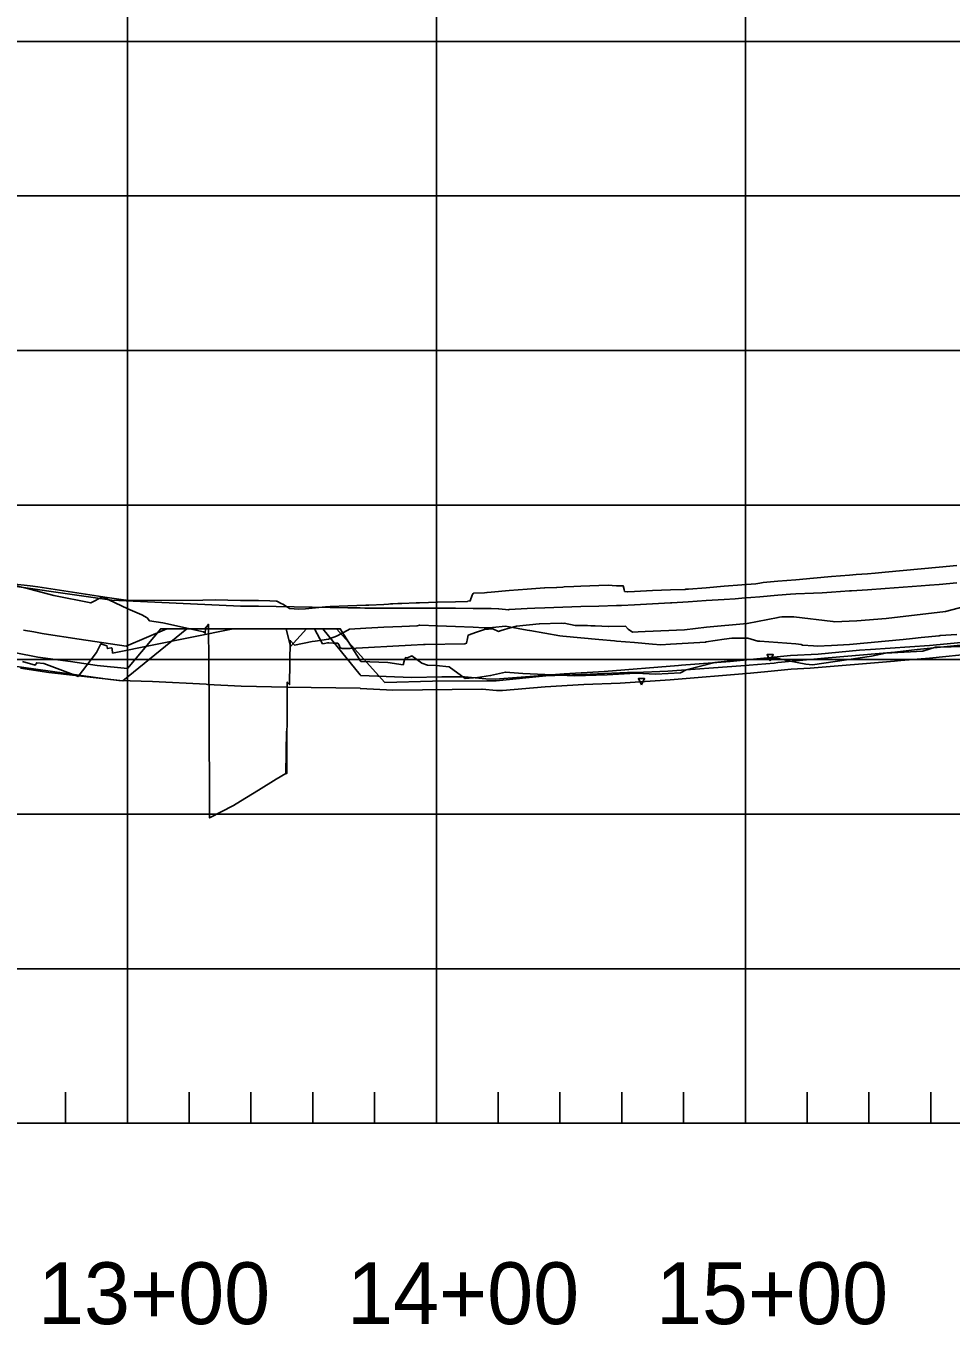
# Model space of a CAD drawing. Extents: x 704797 to 712284, y 374940 to 376945.
# Drawn here: x 708400.9 to 708700.2, y 375160.2 to 375580.5 of the extents above; entities that cross this region are included whole.
import ezdxf

# ---------------------------------------------------------------- set-up
doc = ezdxf.new("R2010")
doc.units = 0
for name, color, linetype in [('10', 7, 'Continuous'), ('12', 7, 'Continuous'), ('13', 7, 'Continuous'), ('61', 7, 'Continuous'), ('63', 7, 'Continuous'), ('Existing', 7, 'Continuous')]:
    doc.layers.add(name, color=color, linetype=linetype)

msp = doc.modelspace()

# ---------------------------------------------------------------- linework, layer by layer
at = {"layer": '10'}
for points in [[(708715.31, 375395.49), (708698.44, 375391.04), (708679.27, 375388.8), (708669.77, 375388.06), (708662.47, 375387.69), (708662.05, 375387.83), (708649.33, 375389.29), (708645.46, 375389.29), (708644.75, 375389.2), (708644.28, 375389.12), (708634.22, 375387.2), (708621.16, 375386), (708614.04, 375385.15), (708601.26, 375384.58), (708599.05, 375384.46), (708597.12, 375384.35), (708596.73, 375384.68), (708596.17, 375385.04), (708595.73, 375385.27), (708594.9, 375386.27), (708589.46, 375386.18), (708589.43, 375386.18), (708585.05, 375386.37), (708583.67, 375386.45), (708582.63, 375386.49), (708579.54, 375386.55), (708578.61, 375386.54), (708575.1, 375387.21), (708574.98, 375387.2), (708574.08, 375387.29), (708567.06, 375387.06), (708566.99, 375387.03), (708559.61, 375386.34), (708557.61, 375385.77), (708554.7, 375384.86), (708553.84, 375384.6), (708551.96, 375385.43), (708549.23, 375385.21), (708546.67, 375384.34), (708544, 375383.42), (708543.78, 375382.31), (708543.49, 375380.83), (708542.9, 375380.62), (708530.03, 375380.32), (708529.52, 375380.31), (708525.52, 375380.18), (708505.77, 375379.09), (708503.24, 375379.01), (708502.6, 375379.26), (708502.55, 375379.27), (708502.25, 375380.16), (708501.76, 375380.78), (708500.3, 375380.84), (708498.9, 375380.87), (708498.47, 375380.88), (708497.45, 375380.69), (708496.86, 375380.59), (708494.26, 375385.47), (708493.75, 375385.47), (708493.25, 375385.47), (708492.78, 375385.47), (708492.44, 375385.47), (708492.34, 375385.47), (708491.68, 375385.47), (708486.45, 375379.69), (708485.13, 375385.47), (708483.66, 375385.47), (708482.96, 375385.47), (708482.26, 375385.47), (708480.13, 375385.47), (708470.9, 375385.47), (708456.29, 375385.47), (708446.43, 375385.47), (708433.3, 375379.83), (708433.25, 375379.82), (708418.07, 375382.11), (708406.74, 375383.82), (708406.15, 375383.91), (708403.38, 375384.42), (708400.09, 375384.97)], [(708399.74, 375374.83), (708403.87, 375373.68), (708404.35, 375374.46), (708406.66, 375374.26), (708416.18, 375370.6), (708417.75, 375369.99), (708423.72, 375377.78), (708425.07, 375380.6), (708427.06, 375379.94), (708427.24, 375379.04), (708428.49, 375379.28), (708428.63, 375379.15), (708428.73, 375378.94), (708428.88, 375377.56), (708467.92, 375385.47), (708502.56, 375385.47), (708509.27, 375374.88), (708518.03, 375374.57), (708522.92, 375373.81), (708523.34, 375375.43), (708523.77, 375376.13), (708524.36, 375376.02), (708525.71, 375376.64), (708528.99, 375374.37), (708530.85, 375373.63), (708533.58, 375373.54), (708537.78, 375373.12), (708543.02, 375369.34), (708546.99, 375369.68), (708551.22, 375370.29), (708556.01, 375371.41), (708561.7, 375370.97), (708578.43, 375370.22), (708589, 375370.55), (708598.16, 375371.04), (708598.39, 375371.05), (708604.7, 375370.79), (708612.65, 375371.23), (708614.53, 375372.14), (708623.8, 375374.49), (708627.82, 375374.94), (708643.39, 375376.09), (708647.69, 375375.08), (708653.26, 375373.97), (708655.37, 375373.74), (708674.49, 375376.61), (708679.08, 375377.54), (708691.09, 375378.17), (708695.19, 375379.52), (708715.38, 375379.96)]]:
    msp.add_lwpolyline(points, dxfattribs=at)
at = {"layer": '12'}
for points in [[(708390.95, 375378.92), (708404.72, 375376.29), (708415.31, 375374.83), (708423.93, 375373.56), (708433.76, 375372.55), (708444.47, 375385.47), (708445.33, 375385.47), (708468.35, 375385.47), (708470.13, 375385.47), (708496.9, 375385.47), (708509.01, 375370.49), (708509.22, 375370.32), (708525.68, 375369.67), (708535.51, 375369.87), (708542.67, 375369.91), (708542.81, 375369.91), (708549.73, 375369.2), (708552.77, 375369.13), (708575.08, 375370.92), (708588, 375371.61), (708612.07, 375373.53), (708612.99, 375373.62), (708628.75, 375374.81), (708648.3, 375376.79), (708657.22, 375377.28), (708670.59, 375378.5), (708674.2, 375378.72), (708693.31, 375380.02), (708716.04, 375382.23)], [(708395.49, 375373.52), (708422.66, 375369.78), (708426.55, 375369.21), (708430.96, 375368.76), (708441.77, 375368.35), (708459.24, 375367.49), (708459.57, 375367.47), (708470.52, 375366.92), (708485.24, 375366.56), (708509, 375366.22), (708509.12, 375366.12), (708519.62, 375365.63), (708548.44, 375365.95), (708548.54, 375365.95), (708553.12, 375365.52), (708555.09, 375365.49), (708568.92, 375366.69), (708581.41, 375367.43), (708593.17, 375367.87), (708609.3, 375368.92), (708635.35, 375371.06), (708640.95, 375371.66), (708648.48, 375372.38), (708654.71, 375372.69), (708682, 375375.01), (708683.97, 375375.19), (708693.32, 375375.9), (708708.03, 375377.45)]]:
    msp.add_lwpolyline(points, dxfattribs=at)
for points in [[(708641.73, 375375.12), (708640.73, 375377.12), (708642.73, 375377.12)], [(708600.06, 375367.32), (708599.06, 375369.32), (708601.06, 375369.32)]]:
    msp.add_lwpolyline(points, close=True, dxfattribs=at)
at = {"layer": '13'}
msp.add_lwpolyline([(708704.38, 375380.21), (708689.31, 375378.72), (708682.01, 375377.86), (708660.47, 375376.08), (708644.16, 375374.53), (708642.99, 375374.33), (708632.24, 375373.45), (708608.63, 375371.72), (708598.12, 375371.25), (708595.67, 375371.27), (708595.53, 375371.32), (708590.46, 375371.13), (708583.47, 375370.8), (708569.07, 375370.17), (708553.09, 375368.63), (708549.99, 375368.62), (708532.43, 375368.5), (708517.04, 375368.09), (708501.37, 375385.47), (708493.22, 375385.47), (708484.06, 375385.47), (708479.9, 375385.47), (708478.58, 375385.47), (708473.17, 375385.47), (708461.25, 375385.47), (708452.91, 375385.47), (708432.27, 375368.56), (708408.28, 375371.35), (708399.09, 375372.68)], dxfattribs=at)
at = {"layer": '61'}
for p, q in [((708433.69, 375225.47), (708433.69, 375925.47)), ((708533.69, 375225.47), (708533.69, 375925.47)), ((708633.69, 375225.47), (708633.69, 375925.47)), ((708133.69, 375575.47), (712133.69, 375575.47)), ((708133.69, 375525.47), (712133.69, 375525.47)), ((708133.69, 375475.47), (712133.69, 375475.47)), ((708133.69, 375425.47), (712133.69, 375425.47)), ((708133.69, 375375.47), (712133.69, 375375.47)), ((708133.69, 375325.47), (712133.69, 375325.47)), ((708133.69, 375275.47), (712133.69, 375275.47)), ((708413.69, 375225.47), (708413.69, 375235.47)), ((708453.69, 375225.47), (708453.69, 375235.47)), ((708473.69, 375225.47), (708473.69, 375235.47)), ((708493.69, 375225.47), (708493.69, 375235.47)), ((708513.69, 375225.47), (708513.69, 375235.47)), ((708553.69, 375225.47), (708553.69, 375235.47)), ((708573.69, 375225.47), (708573.69, 375235.47)), ((708593.69, 375225.47), (708593.69, 375235.47)), ((708613.69, 375225.47), (708613.69, 375235.47)), ((708653.69, 375225.47), (708653.69, 375235.47)), ((708673.69, 375225.47), (708673.69, 375235.47)), ((708693.69, 375225.47), (708693.69, 375235.47)), ((708133.69, 375225.47), (712133.69, 375225.47))]:
    msp.add_line(p, q, dxfattribs=at)
at = {"layer": '63'}
for points in [[(708396.31, 375399.96), (708402.19, 375399.38), (708403.11, 375399.25), (708404.73, 375399), (708427.2, 375395.59), (708433.24, 375394.68), (708433.26, 375394.68), (708438.24, 375394.6), (708458.11, 375394.72), (708462.14, 375394.76), (708470.29, 375394.64), (708476.09, 375394.56), (708479.78, 375394.5), (708481.88, 375394.37), (708482.11, 375394.35), (708483.48, 375393.67), (708483.98, 375393.44), (708485.56, 375392.42), (708486.13, 375392.01), (708487.62, 375391.88), (708487.68, 375391.88), (708489.06, 375391.74), (708491.36, 375391.88), (708493.48, 375392.1), (708497.86, 375392.54), (708499.27, 375392.6), (708505.07, 375392.84), (708510.87, 375393.07), (708511.84, 375393.11), (708516.66, 375393.34), (708518.22, 375393.42), (708518.86, 375393.47), (708519.57, 375393.49), (708521.27, 375393.6), (708522.46, 375393.65), (708527.2, 375393.83), (708528.26, 375393.86), (708534.05, 375394.03), (708539.85, 375394.2), (708543.75, 375394.3), (708543.87, 375394.34), (708544.63, 375394.44), (708544.63, 375394.44), (708545.23, 375396.31), (708545.41, 375396.54), (708545.65, 375396.84), (708545.72, 375396.93), (708549.25, 375397.03), (708550.1, 375397.21), (708551.44, 375397.32), (708557.24, 375397.78), (708563.04, 375398.23), (708568.64, 375398.65), (708568.83, 375398.65), (708572.57, 375398.8), (708572.65, 375398.85), (708574.63, 375398.95), (708575.06, 375398.97), (708578.2, 375399.15), (708580.43, 375399.24), (708586.22, 375399.44), (708589.31, 375399.54), (708590.53, 375399.48), (708592.02, 375399.37), (708593.2, 375399.29), (708594.12, 375399.34), (708594.43, 375398.15), (708594.58, 375397.52), (708595.46, 375397.45), (708595.58, 375397.44), (708597.82, 375397.53), (708603.61, 375397.78), (708609.41, 375398.01), (708614.12, 375398.2), (708614.22, 375398.2), (708614.27, 375398.2), (708614.3, 375398.2), (708614.34, 375398.21), (708614.36, 375398.21), (708614.37, 375398.21), (708614.44, 375398.21), (708614.46, 375398.21), (708614.68, 375398.23), (708615.21, 375398.27), (708615.29, 375398.28), (708621, 375398.74), (708626.8, 375399.21), (708632.6, 375399.66), (708637.04, 375400.01), (708638.39, 375400.23), (708639.46, 375400.41), (708644.19, 375400.83), (708649.99, 375401.33), (708655.78, 375401.83), (708661.58, 375402.33), (708667.38, 375402.81), (708669.54, 375402.99), (708673.17, 375403.24), (708675.65, 375403.41), (708678.97, 375403.74), (708684.77, 375404.3), (708690.56, 375404.85), (708696.36, 375405.39), (708702.16, 375405.92)], [(708393.42, 375400.42), (708402.1, 375398.3), (708409.9, 375396.19), (708421.82, 375393.81), (708425.65, 375395.76), (708433.8, 375391.86), (708438.35, 375390), (708440.14, 375388.98), (708440.82, 375388.06), (708445.15, 375387.33), (708458.37, 375384.41), (708458.82, 375384), (708458.94, 375385.58), (708459.02, 375385.9), (708459.18, 375385.9), (708459.97, 375386.89), (708460.13, 375360.64), (708460.3, 375324.27), (708468.08, 375328.26), (708470.29, 375329.65), (708476.09, 375333.19), (708481.88, 375336.74), (708484.93, 375338.61), (708485.21, 375352.32), (708485.29, 375338.58), (708485.43, 375368.22), (708486.16, 375367.41), (708486.36, 375381.57), (708486.52, 375381.55), (708487.68, 375380.24), (708487.74, 375380.17), (708493.48, 375381.3), (708494.47, 375381.48), (708498.75, 375382.09), (708499.27, 375382.29), (708501.42, 375383.05), (708505.07, 375385.01), (708505.62, 375385.3), (708510.87, 375385.64), (708516.66, 375385.97), (708522.46, 375386.23), (708527.43, 375386.41), (708528.26, 375386.57), (708528.31, 375386.58), (708534.05, 375386.42), (708539.85, 375386.2), (708545.65, 375385.94), (708549.19, 375385.75), (708551.44, 375385.8), (708551.88, 375385.81), (708556.01, 375386.33), (708557.24, 375386.11), (708563.04, 375385.01), (708563.91, 375384.84), (708568.83, 375383.99), (708573.68, 375383.13), (708574.63, 375383.05), (708580.43, 375382.55), (708586.22, 375382.01), (708591.32, 375381.51), (708592.02, 375381.46), (708597.82, 375380.98), (708603.61, 375380.47), (708606.38, 375380.21), (708609.41, 375380.42), (708615.21, 375380.8), (708620.81, 375381.14), (708621, 375381.17), (708626.8, 375382.03), (708629.26, 375382.38), (708632.6, 375382.42), (708634.54, 375382.44), (708637.68, 375381.43), (708638.39, 375381.39), (708644.19, 375380.98), (708649.99, 375380.55), (708651.78, 375380.41), (708652.17, 375380.13), (708655.78, 375379.88), (708656.92, 375379.8), (708661.58, 375380.06), (708667.38, 375380.37), (708667.42, 375380.37), (708673.17, 375380.94), (708678.97, 375381.48), (708684.77, 375382.01), (708687.81, 375382.28), (708690.56, 375382.58), (708696.36, 375383.19), (708696.75, 375383.23), (708702.16, 375383.62)]]:
    msp.add_lwpolyline(points, dxfattribs=at)
at = {"layer": 'Existing'}
msp.add_lwpolyline([(708385.66, 375400.89), (708428.69, 375394.74), (708470.29, 375392.8), (708470.92, 375392.77), (708470.92, 375392.77), (708470.92, 375392.77), (708470.92, 375392.77), (708476.09, 375392.71), (708481.88, 375392.63), (708487.68, 375392.55), (708493.48, 375392.46), (708499.27, 375392.37), (708505.07, 375392.26), (708508.99, 375392.19), (708509, 375392.18), (708510.53, 375392.1), (708510.87, 375392.1), (708516.66, 375392.11), (708522.46, 375392.11), (708528.26, 375392.11), (708534.05, 375392.09), (708539.85, 375392.06), (708545.65, 375392.01), (708551.44, 375391.96), (708553.83, 375391.94), (708553.87, 375391.94), (708556.01, 375391.66), (708556.99, 375391.61), (708557.24, 375391.63), (708563.04, 375391.98), (708565.51, 375392.12), (708568.83, 375392.23), (708574.63, 375392.42), (708580.43, 375392.6), (708586.22, 375392.77), (708592.02, 375392.93), (708593.56, 375392.97), (708597.82, 375393.2), (708603.61, 375393.51), (708609.41, 375393.81), (708609.92, 375393.83), (708615.21, 375394.18), (708621, 375394.55), (708626.8, 375394.91), (708630.44, 375395.13), (708632.6, 375395.32), (708638.39, 375395.83), (708644.19, 375396.33), (708648.27, 375396.68), (708649.99, 375396.75), (708655.78, 375396.97), (708658.53, 375397.07), (708661.58, 375397.28), (708667.38, 375397.67), (708668.09, 375397.71), (708673.17, 375398.09), (708678.97, 375398.51), (708684.77, 375398.92), (708690.56, 375399.32), (708693.3, 375399.51), (708696.36, 375399.8), (708702.16, 375400.36)], dxfattribs=at)

# ---------------------------------------------------------------- texts
at = {"layer": '61'}
for s, p in [('13+00', (708404.77, 375160.47)), ('14+00', (708504.77, 375160.47)), ('15+00', (708604.77, 375160.47))]:
    msp.add_text(s, height=20, dxfattribs=at).set_placement(p)

doc.saveas('drawing.dxf')
